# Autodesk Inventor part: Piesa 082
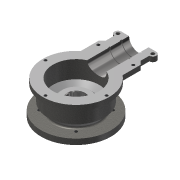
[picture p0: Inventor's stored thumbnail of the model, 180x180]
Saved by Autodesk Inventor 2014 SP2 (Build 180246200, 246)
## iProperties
Created: 2009-02
Part Number: Piesa 082
Document SubType Name: Modeling
Designer: Costel
Material: Steel, Cast
Density: 7.85 g/cm^3
Appearance: Steel - Cast
Author: Costel
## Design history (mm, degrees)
sketch "Sketch2"
  geometry: L1 (0, -5)-(0, 65) reference; L2 (5, 0)-(-65, 0) reference; L3 (0, 0)-(-46, 0); L4 (-47.5, 50)-(0, 50); L5 (-50, 10)-(-34.328, 10); L6 (-32.914, 13.414)-(-40.5, 21); L7 (-40.5, 21)-(-40.5, 43); L8 (-40.5, 43)-(-47.5, 43); L9 (-50, 2)-(-50, 10); L10 (-47.5, 43)-(-47.5, 50); L11 (0, 0)-(0, 50); L12 (-46, 0)-(-50, 2); A1 r 2 centre (-34.328, 12) between (-34.328, 10) and (-32.914, 13.414)
  constraints: 20 end point, 6 perpendicular, 3 parallel, 3 point on line, 2 point on circle, 2 tangent, 1 centre point, 1 collinear
  dimensions: "d0" = 45 deg angle of L6 L5; "d1" = 2 radius of A1; "d2" = 4 horizontal distance of L3.end L9.start; "d3" = 2 vertical distance of L3.end L9.start; "d4" = 100 diameter of L9 L1; "d5" = 50 distance between parallel lines of L3 L4; "d6" = 7 distance of L8.end L4.start; "d7" = 29 distance from line of L4 L6.end; "d8" = 10 distance between parallel lines of L3 L5; "d9" = 95 diameter of L10 L1; "d10" = 81 diameter of L7 L1
revolve "Revolution1" sketch "Sketch2" stored, may be unused: angle "d11" = 90 deg
sketch "Sketch4"
  geometry: L1 (0, -60)-(0, 80) reference; L2 (-60, 0)-(80, 0) reference; L3 (17.5, 83)-(21.5, 83); L4 (21.5, 83)-(21.5, 0); L5 (21.5, 0)-(0, 0); L6 (0, 0)-(0, 90); L7 (0, 90)-(17.5, 90); L8 (17.5, 90)-(17.5, 83)
  constraints: 12 end point, 2 horizontal, 2 parallel, 2 perpendicular, 2 point on line, 1 collinear
  dimensions: "d17" = 7 distance between parallel lines of L7 L3; "d18" = 90 distance between parallel lines of L2 L7; "d19" = 35 diameter of L8 L1; "d20" = 43 diameter of L4 L1
revolve "Revolution3" sketch "Sketch4" stored, may be unused: angle "d21" = 180 deg
sketch "Sketch5"
  geometry: L1 (0, 7)-(-35, 7) reference; L2 (-17.5, -147)-(-17.5, 49) reference; L3 (7.5, 7)-(-42.5, 7); L4 (7.5, -3)-(7.5, -15.5); L5 (12.5, -83)-(-47.5, -83); L6 (-42.5, -3)-(-42.5, -15.5); L7 (7.5, -15.5)-(12.5, -20.5); L8 (12.5, -20.5)-(12.5, -83); L9 (-42.5, -15.5)-(-47.5, -20.5); L10 (-47.5, -20.5)-(-47.5, -83); L11 (-77.5, -83)-(62.5, -83) reference; C1 r 2.5 at (-42.5, 2); C2 r 2.5 at (7.5, 2); A1 r 5 centre (7.5, 2) between (7.5, -3) and (7.5, 7); A2 r 5 centre (-42.5, 2) between (-42.5, 7) and (-42.5, -3)
  constraints: 16 end point, 6 symmetric about line, 4 centre point, 4 point on circle, 2 coincident, 2 parallel, 2 perpendicular, 2 tangent, 1 collinear, 1 equal radius, 1 vertical alignment, 1 other
  dimensions: "d22" = 5 radius of A1; "d23" = 50 distance of A1.centre A2.centre; "d24" = 67.5 distance from line of L5 L6.end; "d25" = 5 horizontal distance of L6.end L9.end; "d26" = 60 distance between parallel lines of L8 L10; "d27" = 5 diameter of C1
extrude "Extrusion1" join sketch "Sketch5" distance "d31" = 7; taper "d32" = 0 deg
sketch "Sketch6"
  geometry: L1 (0, -5)-(0, 65) reference; L2 (36.827, 50)-(36.827, 50) reference; L3 (62.5, 50)-(36.827, 50) reference; L4 (67.5, 50)-(62.5, 50) reference; L5 (80, 50)-(67.5, 50) reference; L6 (90, 50)-(80, 50) reference; L7 (80, 50)-(90, 50) reference; L8 (67.5, 50)-(80, 50) reference; L9 (62.5, 50)-(67.5, 50) reference; L10 (36.827, 50)-(62.5, 50) reference; L11 (82.5, 50)-(87.5, 50) reference; L12 (82.5, 50)-(87.5, 50) reference; L13 (-64, 0)-(132, 0) reference; L14 (36.827, 50)-(-47.5, 50) reference; L15 (-33, 50)-(-33, 25); L16 (-33, 25)-(-26.5, 18.5); L17 (-26.5, 18.5)-(-20, 25); L18 (-20, 25)-(-13, 25); L19 (-12, 24)-(-12, 9); L20 (-12, 9)-(-13, 9); L21 (-13, 9)-(-13, 7); L22 (-13, 7)-(-12, 7); L23 (-12, 7)-(-12, 0); L24 (-12, 0)-(0, 0); L25 (0, 0)-(0, 50); L26 (0, 50)-(-33, 50); L27 (-13, 25)-(-12, 24); 1 further point
  constraints: 26 end point, 8 point on line, 4 parallel, 3 perpendicular, 2 collinear, 1 horizontal alignment
  dimensions: "d33" = 90 deg angle of L17 L16; "d34" = 1 distance of L18.end point (-12, 25); "d35" = 1 distance of L19.start point (-12, 25) (= d34); "d36" = 7 distance of L22.end L23.end; "d37" = 2 distance of L20.end L21.end; "d38" = 66 diameter of L15 L1; "d39" = 53 diameter of L16.end L1; "d40" = 135 deg angle of L18 L17; "d41" = 24 diameter of L23 L1; "d42" = 26 diameter of L21 L1; "d45" = 25 distance between parallel lines of L14 L18
revolve "Revolution4" sketch "Sketch6" stored, may be unused: angle "d46" = 180 deg
sketch "Sketch7"
  geometry: L1 (-33, 50)-(33, 50) reference; L2 (90, 32.5)-(90, 43) reference; L3 (0, 50)-(90, 50); L4 (90, 50)-(90, 36); L5 (0, -5)-(0, 65) reference; L6 (90, 36)-(80, 36); L7 (80, 36)-(80, 35); L8 (80, 35)-(78, 35); L9 (78, 35)-(78, 36); L10 (78, 36)-(63, 36); L11 (63, 36)-(63, 35); L12 (63, 35)-(61, 35); L13 (61, 35)-(61, 36); L14 (61, 36)-(0, 36); L15 (0, 36)-(0, 50)
  constraints: 24 end point, 6 collinear, 6 perpendicular, 5 parallel, 2 point on line
  dimensions: "d47" = 28 diameter of L6 L3; "d48" = 30 diameter of L8 L3; "d49" = 10 distance between parallel lines of L4 L7; "d50" = 2 distance of L7.end L8.end; "d51" = 15 distance of L9.end L10.end; "d52" = 2 distance of L11.end L12.end (= d50)
revolve "Revolution5" sketch "Sketch7" stored, may be unused: angle "d53" = 180 deg
sketch "Sketch8"
  geometry: L1 (30, -114.827)-(30, 81.173) reference; L2 (-40, -36.827)-(100, -36.827) reference; A1 r 5 centre (5, 48.173) between (5, 53.173) and (5, 43.173) reference; A2 r 5 centre (55, 48.173) between (55, 43.173) and (55, 53.173) reference; 5 further points
  constraints: 3 point on line, 2 vertical alignment, 1 horizontal alignment, 1 symmetric about line
  dimensions: "d54" = 28 distance of A1.centre point (5, 20.173); "d55" = 87.5 distance of point (73.75, -36.827) point (-13.75, -36.827); "d56" = 43.75 distance from line of L2 point (30, -80.577) (= 0.5 x d55)
hole "Hole1" sketch "Sketch8" at (5, 20.173), (55, 20.173), (-13.75, -36.827), (30, -80.577), (73.75, -36.827) diameter "d57" = 4.134; stored, may be unused: countersink angle "d61" = 90 deg, drill point angle "d63" = 118 deg; dims "d58" = 6, "d59" = 4, "d60" = 2, "d62" = 8
sketch "Sketch9"
  geometry: L1 (0, -64)-(0, 132) reference; L2 (-60, 0)-(80, 0) reference; L3 (0, 0)-(26.517, -26.517); 1 further point
  constraints: 2 end point, 2 point on line, 1 coincident
  dimensions: "d64" = 37.5 distance of L3.start L3.end; "d65" = 45 deg angle of L1 L3
hole "Hole2" sketch "Sketch9" at (26.517, -26.517) diameter "d66" = 4.134; stored, may be unused: countersink angle "d70" = 90 deg, drill point angle "d72" = 118 deg; dims "d67" = 6, "d68" = 4, "d69" = 2, "d71" = 8
pattern_circular "Circular Pattern1" dims angle "d74" = 360 deg
body "Solid1"
node "Projected Loop1"
